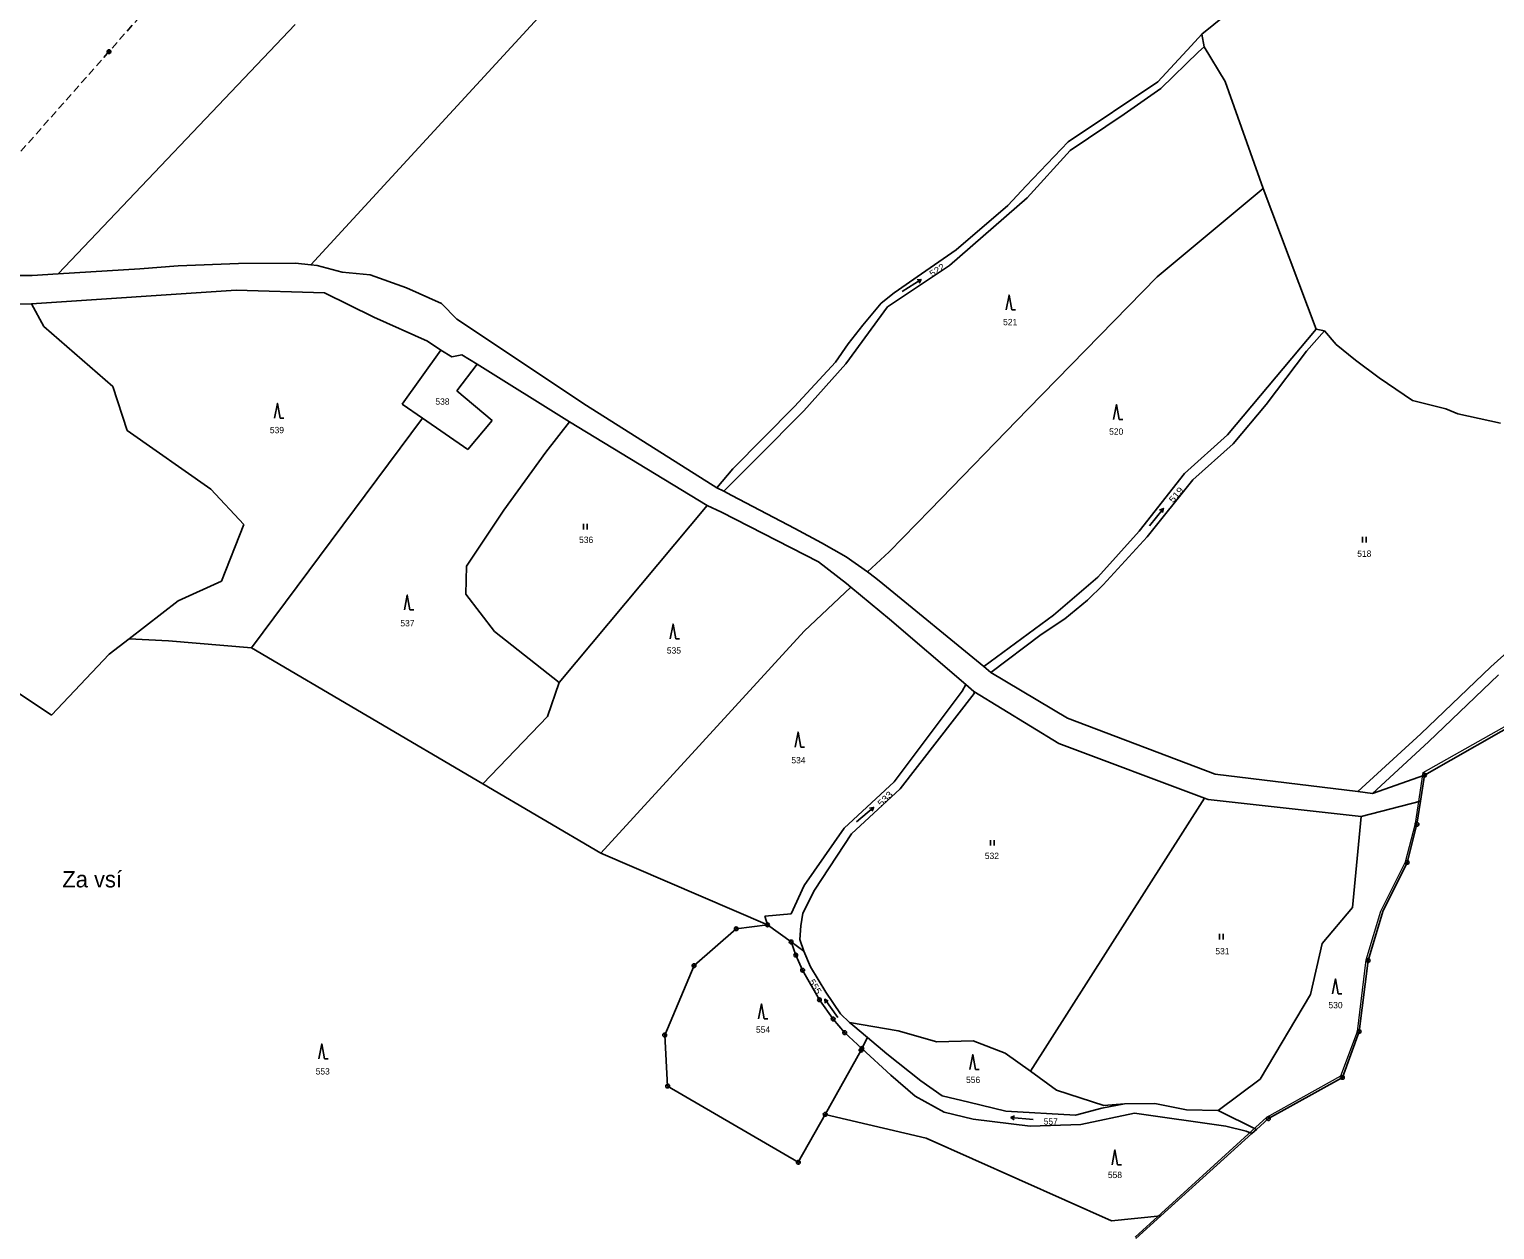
# Model space of a CAD drawing. Extents: x -653193 to -651624, y -1092017 to -1090260.
# Drawn here: x -652409.3 to -652015.8, y -1091464 to -1091141.6 of the extents above; entities that cross this region are included whole.
import ezdxf
from ezdxf.enums import TextEntityAlignment as Align

# ---------------------------------------------------------------- set-up
doc = ezdxf.new("R2010")
doc.units = 0
doc.header["$LTSCALE"] = 0.68
doc.linetypes.add('MEDIUM_DASHED', pattern=[4.5, 3, -1.5])
for name, color, linetype, lineweight in [('1', 7, 'Continuous', 25), ('3', 7, 'Continuous', 25), ('4', 7, 'Continuous', 13), ('6', 7, 'Continuous', 25), ('7', 7, 'Continuous', 13), ('8', 7, 'Continuous', 25)]:
    doc.layers.add(name, color=color, linetype=linetype, lineweight=lineweight)
doc.layers.add('2', color=7, linetype='Continuous')

msp = doc.modelspace()

# ---------------------------------------------------------------- linework, layer by layer
at = {"layer": '1'}
for p, q in [((-652228.92, -1091090.97), (-652333.63, -1091204.87)), ((-652079.85, -1091131.06), (-652094.43, -1091142.88)), ((-652337.88, -1091140.35), (-652401.48, -1091207.32)), ((-652094.43, -1091142.88), (-652097.36, -1091146.07)), ((-652094.43, -1091142.88), (-652093.86, -1091146.31)), ((-652097.36, -1091146.07), (-652106.25, -1091155.76)), ((-652095.39, -1091147.7), (-652105.44, -1091157.47)), ((-652095.39, -1091147.7), (-652093.86, -1091146.31)), ((-652093.86, -1091146.31), (-652088.2, -1091155.67)), ((-652106.25, -1091155.76), (-652130.38, -1091171.83)), ((-652088.2, -1091155.67), (-652077.99, -1091184.36)), ((-652105.44, -1091157.47), (-652115.27, -1091164.38)), ((-652115.27, -1091164.38), (-652129.82, -1091174.14)), ((-652141.61, -1091183.64), (-652130.38, -1091171.83)), ((-652129.82, -1091174.14), (-652141.35, -1091186.91)), ((-652146.54, -1091188.95), (-652141.61, -1091183.64)), ((-652141.35, -1091186.91), (-652162.19, -1091205.06)), ((-652106.45, -1091208.06), (-652077.99, -1091184.36)), ((-652077.99, -1091184.36), (-652063.78, -1091222.16)), ((-652160.45, -1091200.81), (-652146.54, -1091188.95)), ((-652169.72, -1091207.28), (-652160.45, -1091200.81)), ((-652401.48, -1091207.32), (-652408.46, -1091207.73)), ((-652379.6, -1091205.91), (-652401.48, -1091207.32)), ((-652369.33, -1091205.1), (-652379.6, -1091205.91)), ((-652353.05, -1091204.48), (-652369.33, -1091205.1)), ((-652337.79, -1091204.41), (-652353.05, -1091204.48)), ((-652333.63, -1091204.87), (-652337.79, -1091204.41)), ((-652331.97, -1091205.06), (-652333.63, -1091204.87)), ((-652325.27, -1091206.83), (-652331.97, -1091205.06)), ((-652317.78, -1091207.57), (-652325.27, -1091206.83)), ((-652162.19, -1091205.06), (-652178.85, -1091216.18)), ((-652177.03, -1091212.4), (-652169.72, -1091207.28)), ((-652408.46, -1091207.73), (-652457.25, -1091207.83)), ((-652308.03, -1091211.02), (-652317.78, -1091207.57)), ((-652298.61, -1091215.29), (-652308.03, -1091211.02)), ((-652141.13, -1091243.67), (-652106.45, -1091208.06)), ((-652408.71, -1091215.36), (-652486.99, -1091216.11)), ((-652353.69, -1091211.67), (-652408.71, -1091215.36)), ((-652405.35, -1091221.4), (-652408.71, -1091215.36)), ((-652329.96, -1091212.41), (-652353.69, -1091211.67)), ((-652316.74, -1091218.93), (-652329.96, -1091212.41)), ((-652294.44, -1091219.47), (-652298.61, -1091215.29)), ((-652185.51, -1091221.05), (-652180.51, -1091215.2)), ((-652180.51, -1091215.2), (-652177.03, -1091212.4)), ((-652302.39, -1091225.39), (-652316.74, -1091218.93)), ((-652178.85, -1091216.18), (-652190.02, -1091231.46)), ((-652386.83, -1091237.58), (-652405.35, -1091221.4)), ((-652259.65, -1091242.61), (-652294.44, -1091219.47)), ((-652189.45, -1091226.12), (-652185.51, -1091221.05)), ((-652063.78, -1091222.16), (-652087.59, -1091250.54)), ((-652066.34, -1091228.02), (-652061.56, -1091222.57)), ((-652063.78, -1091222.16), (-652061.56, -1091222.57)), ((-652061.56, -1091222.57), (-652058.38, -1091226.27)), ((-652298.78, -1091227.76), (-652302.39, -1091225.39)), ((-652192.79, -1091231.03), (-652189.45, -1091226.12)), ((-652058.38, -1091226.27), (-652053.18, -1091230.52)), ((-652298.78, -1091227.76), (-652309.11, -1091242.27)), ((-652295.85, -1091229.62), (-652298.78, -1091227.76)), ((-652293.09, -1091229.03), (-652295.85, -1091229.62)), ((-652289.05, -1091231.55), (-652293.09, -1091229.03)), ((-652203.79, -1091242.9), (-652192.79, -1091231.03)), ((-652077.15, -1091242.41), (-652066.34, -1091228.02)), ((-652053.18, -1091230.52), (-652046.86, -1091235.25)), ((-652294.48, -1091238.72), (-652289.05, -1091231.55)), ((-652264.25, -1091247.08), (-652289.05, -1091231.55)), ((-652190.02, -1091231.46), (-652201.3, -1091244.07)), ((-652382.98, -1091249.35), (-652386.83, -1091237.58)), ((-652284.97, -1091246.66), (-652294.48, -1091238.72)), ((-652046.86, -1091235.25), (-652037.91, -1091241.32)), ((-652309.11, -1091242.27), (-652303.7, -1091246.05)), ((-652259.65, -1091242.61), (-652224.71, -1091264.77)), ((-652220.4, -1091259.62), (-652203.79, -1091242.9)), ((-652086.07, -1091252.93), (-652077.15, -1091242.41)), ((-652037.91, -1091241.32), (-652028.98, -1091243.53)), ((-652303.7, -1091246.05), (-652349.62, -1091307.76)), ((-652303.7, -1091246.05), (-652291.55, -1091254.5)), ((-652291.55, -1091254.5), (-652284.97, -1091246.66)), ((-652201.3, -1091244.07), (-652213.85, -1091256.68)), ((-652167.42, -1091270.66), (-652141.13, -1091243.67)), ((-652028.98, -1091243.53), (-652025.75, -1091244.89)), ((-652025.75, -1091244.89), (-652014.28, -1091247.38)), ((-652360.49, -1091265.09), (-652382.98, -1091249.35)), ((-652270.6, -1091255.17), (-652264.25, -1091247.08)), ((-652227.23, -1091269.48), (-652264.25, -1091247.08)), ((-652087.59, -1091250.54), (-652099.1, -1091260.92)), ((-652096.85, -1091262.6), (-652086.07, -1091252.93)), ((-652281.84, -1091270.75), (-652270.6, -1091255.17)), ((-652213.85, -1091256.68), (-652222.81, -1091265.7)), ((-652224.71, -1091264.77), (-652220.4, -1091259.62)), ((-652099.1, -1091260.92), (-652111.26, -1091276.41)), ((-652351.65, -1091274.6), (-652360.49, -1091265.09)), ((-652224.71, -1091264.77), (-652222.81, -1091265.7)), ((-652222.81, -1091265.7), (-652220.6, -1091266.79)), ((-652109.12, -1091277.93), (-652096.85, -1091262.6)), ((-652227.23, -1091269.48), (-652267.04, -1091317.02)), ((-652223.42, -1091271.32), (-652227.23, -1091269.48)), ((-652220.6, -1091266.79), (-652203.73, -1091275.7)), ((-652291.88, -1091285.81), (-652281.84, -1091270.75)), ((-652197.39, -1091284.63), (-652223.42, -1091271.32)), ((-652178.38, -1091281.91), (-652167.42, -1091270.66)), ((-652357.7, -1091289.87), (-652351.65, -1091274.6)), ((-652203.73, -1091275.7), (-652196.57, -1091279.52)), ((-652111.26, -1091276.41), (-652122.39, -1091288.72)), ((-652120.99, -1091290.79), (-652109.12, -1091277.93)), ((-652196.57, -1091279.52), (-652189.95, -1091283.32)), ((-652184.24, -1091287.36), (-652178.38, -1091281.91)), ((-652292.07, -1091293.3), (-652291.88, -1091285.81)), ((-652189.86, -1091290.44), (-652197.39, -1091284.63)), ((-652189.95, -1091283.32), (-652184.24, -1091287.36)), ((-652369.26, -1091295.14), (-652357.7, -1091289.87)), ((-652184.24, -1091287.36), (-652181.98, -1091289.04)), ((-652181.98, -1091289.04), (-652180.1, -1091290.56)), ((-652122.39, -1091288.72), (-652134.26, -1091299)), ((-652284.37, -1091303.32), (-652292.07, -1091293.3)), ((-652201.23, -1091303.24), (-652188.66, -1091291.44)), ((-652188.66, -1091291.44), (-652189.86, -1091290.44)), ((-652178.33, -1091300.04), (-652188.66, -1091291.44)), ((-652180.1, -1091290.56), (-652152.95, -1091312.77)), ((-652125.18, -1091294.96), (-652120.99, -1091290.79)), ((-652382.43, -1091305.33), (-652369.26, -1091295.14)), ((-652131.28, -1091299.91), (-652125.18, -1091294.96)), ((-652157.79, -1091317.57), (-652178.33, -1091300.04)), ((-652134.26, -1091299), (-652152.95, -1091312.77)), ((-652137.62, -1091304.11), (-652131.28, -1091299.91)), ((-652382.43, -1091305.33), (-652387.79, -1091309.41)), ((-652371.87, -1091305.83), (-652382.43, -1091305.33)), ((-652349.62, -1091307.76), (-652371.87, -1091305.83)), ((-652267.04, -1091317.02), (-652284.37, -1091303.32)), ((-652255.81, -1091362.84), (-652201.23, -1091303.24)), ((-652151.1, -1091314.32), (-652137.62, -1091304.11)), ((-652016.85, -1091312.8), (-652007.17, -1091304.16)), ((-652387.79, -1091309.41), (-652403.34, -1091325.86)), ((-652287.5, -1091344.23), (-652349.62, -1091307.76)), ((-652152.95, -1091312.77), (-652151.1, -1091314.32)), ((-652035.62, -1091330.83), (-652016.85, -1091312.8)), ((-652403.34, -1091325.86), (-652416.58, -1091316.92)), ((-652270.13, -1091326.19), (-652267.04, -1091317.02)), ((-652158.81, -1091319.38), (-652157.79, -1091317.57)), ((-652155.63, -1091319.42), (-652157.79, -1091317.57)), ((-652130.5, -1091326.62), (-652151.1, -1091314.32)), ((-652034.65, -1091341.96), (-651991.83, -1091317.47)), ((-652014.81, -1091315), (-652033.57, -1091333.02)), ((-652177.07, -1091343.7), (-652158.81, -1091319.38)), ((-652155.56, -1091320.01), (-652175.47, -1091345.58)), ((-652155.63, -1091319.42), (-652155.56, -1091320.01)), ((-652132.81, -1091333.44), (-652155.63, -1091319.42)), ((-652287.5, -1091344.23), (-652270.13, -1091326.19)), ((-652090.86, -1091341.62), (-652130.5, -1091326.62)), ((-652052.57, -1091346.36), (-652035.62, -1091330.83)), ((-652033.57, -1091333.02), (-652048.68, -1091346.84)), ((-652093.75, -1091348.11), (-652132.81, -1091333.44)), ((-652255.81, -1091362.84), (-652287.5, -1091344.23)), ((-652190.51, -1091356.19), (-652177.07, -1091343.7)), ((-652052.57, -1091346.36), (-652090.86, -1091341.62)), ((-652048.68, -1091346.84), (-652034.65, -1091341.96)), ((-652035.73, -1091348.93), (-652034.65, -1091341.96)), ((-652175.47, -1091345.58), (-652188.49, -1091357.67)), ((-652140.49, -1091421.45), (-652093.75, -1091348.11)), ((-652092.78, -1091348.48), (-652093.75, -1091348.11)), ((-652051.71, -1091353.06), (-652092.78, -1091348.48)), ((-652048.68, -1091346.84), (-652052.57, -1091346.36)), ((-652035.73, -1091348.93), (-652051.71, -1091353.06)), ((-652036.7, -1091355.13), (-652035.73, -1091348.93)), ((-652051.71, -1091353.06), (-652054.03, -1091377.47)), ((-652201.19, -1091371.59), (-652190.51, -1091356.19)), ((-652039.3, -1091365.37), (-652036.7, -1091355.13)), ((-652188.49, -1091357.67), (-652198.41, -1091372.79)), ((-652211.05, -1091382.12), (-652255.81, -1091362.84)), ((-652045.88, -1091378.54), (-652039.3, -1091365.37)), ((-652204.74, -1091379.18), (-652201.19, -1091371.59)), ((-652198.41, -1091372.79), (-652201.58, -1091378.98)), ((-652211.74, -1091379.78), (-652204.74, -1091379.18)), ((-652211.05, -1091382.12), (-652211.74, -1091379.78)), ((-652201.58, -1091378.98), (-652202.16, -1091382.36)), ((-652054.03, -1091377.47), (-652062.17, -1091387.1)), ((-652049.78, -1091391.7), (-652045.88, -1091378.54)), ((-652230.79, -1091393.09), (-652219.45, -1091383.17)), ((-652219.45, -1091383.17), (-652211.05, -1091382.12)), ((-652204.72, -1091386.73), (-652211.05, -1091382.12)), ((-652202.16, -1091382.36), (-652202.41, -1091386.09)), ((-652203.48, -1091390.25), (-652204.72, -1091386.73)), ((-652204.72, -1091386.73), (-652201.28, -1091389.23)), ((-652202.41, -1091386.09), (-652201.28, -1091389.23)), ((-652062.17, -1091387.1), (-652065.27, -1091400.81)), ((-652201.63, -1091394.33), (-652203.48, -1091390.25)), ((-652201.28, -1091389.23), (-652199.55, -1091393.38)), ((-652052.22, -1091410.79), (-652049.78, -1091391.7)), ((-652238.67, -1091411.72), (-652230.79, -1091393.09)), ((-652197.13, -1091402.26), (-652201.63, -1091394.33)), ((-652199.55, -1091393.38), (-652195.4, -1091400.21)), ((-652195.4, -1091400.21), (-652191.49, -1091405.99)), ((-652193.44, -1091407.42), (-652197.13, -1091402.26)), ((-652065.27, -1091400.81), (-652078.79, -1091423.58)), ((-652190.35, -1091411.08), (-652193.44, -1091407.42)), ((-652191.49, -1091405.99), (-652189.08, -1091408.4)), ((-652237.88, -1091425.42), (-652238.67, -1091411.72)), ((-652185.71, -1091415.32), (-652190.35, -1091411.08)), ((-652175.99, -1091410.63), (-652189.08, -1091408.4)), ((-652189.08, -1091408.4), (-652188.18, -1091409.11)), ((-652188.18, -1091409.11), (-652184.25, -1091412.43)), ((-652165.56, -1091413.51), (-652175.99, -1091410.63)), ((-652056.71, -1091423.1), (-652052.22, -1091410.79)), ((-652195.59, -1091433.03), (-652185.95, -1091415.8)), ((-652185.95, -1091415.8), (-652185.71, -1091415.32)), ((-652185.71, -1091415.32), (-652184.25, -1091412.43)), ((-652177.91, -1091422.47), (-652185.71, -1091415.32)), ((-652184.25, -1091412.43), (-652179.07, -1091416.8)), ((-652155.88, -1091413.31), (-652165.56, -1091413.51)), ((-652147.27, -1091416.57), (-652155.88, -1091413.31)), ((-652179.07, -1091416.8), (-652169.9, -1091423.98)), ((-652140.49, -1091421.45), (-652147.27, -1091416.57)), ((-652171.41, -1091428.14), (-652177.91, -1091422.47)), ((-652133.45, -1091426.52), (-652140.49, -1091421.45)), ((-652078.79, -1091423.58), (-652090.08, -1091432.01)), ((-652076.58, -1091434.18), (-652056.71, -1091423.1)), ((-652202.79, -1091445.9), (-652237.88, -1091425.42)), ((-652169.9, -1091423.98), (-652164.16, -1091428.05)), ((-652120.77, -1091430.69), (-652133.45, -1091426.52)), ((-652163.62, -1091432.46), (-652171.41, -1091428.14)), ((-652164.16, -1091428.05), (-652157.03, -1091429.78)), ((-652157.03, -1091429.78), (-652147.09, -1091432.21)), ((-652128.37, -1091433.26), (-652121.34, -1091431.37)), ((-652121.34, -1091431.37), (-652115.24, -1091430.16)), ((-652115.24, -1091430.16), (-652120.77, -1091430.69)), ((-652115.24, -1091430.16), (-652107.1, -1091430.09)), ((-652107.1, -1091430.09), (-652098.54, -1091431.8)), ((-652195.59, -1091433.03), (-652202.79, -1091445.9)), ((-652168.46, -1091439.44), (-652195.59, -1091433.03)), ((-652155.84, -1091434.32), (-652163.62, -1091432.46)), ((-652140.59, -1091436.23), (-652155.84, -1091434.32)), ((-652147.09, -1091432.21), (-652128.37, -1091433.26)), ((-652112.51, -1091432.69), (-652126.93, -1091435.77)), ((-652087.97, -1091436.16), (-652112.51, -1091432.69)), ((-652098.54, -1091431.8), (-652090.08, -1091432.01)), ((-652090.08, -1091432.01), (-652079.76, -1091437.05)), ((-652079.76, -1091437.05), (-652076.58, -1091434.18)), ((-652118.68, -1091461.65), (-652168.46, -1091439.44)), ((-652126.93, -1091435.77), (-652140.59, -1091436.23)), ((-652105.44, -1091460.25), (-652081.02, -1091438.19)), ((-652082.59, -1091437.55), (-652087.97, -1091436.16)), ((-652081.02, -1091438.19), (-652082.59, -1091437.55)), ((-652081.02, -1091438.19), (-652079.76, -1091437.05)), ((-652105.44, -1091460.25), (-652118.68, -1091461.65)), ((-652112.2, -1091466.36), (-652105.44, -1091460.25))]:
    msp.add_line(p, q, dxfattribs=at)
at = {"layer": '3'}
for p, q in [((-652169.817, -1091208.818), (-652170.38, -1091209.761)), ((-652145.46, -1091216.98), (-652144.464, -1091216.98)), ((-652341.91, -1091246.07), (-652340.914, -1091246.07)), ((-652116.63, -1091246.4), (-652115.634, -1091246.4)), ((-652104.775, -1091270.301), (-652105, -1091271.376)), ((-652260.461, -1091275.95), (-652260.461, -1091274.45)), ((-652259.46, -1091275.95), (-652259.46, -1091274.45)), ((-652051.341, -1091279.43), (-652051.341, -1091277.93)), ((-652050.34, -1091279.43), (-652050.34, -1091277.93)), ((-652307.05, -1091297.57), (-652306.054, -1091297.57)), ((-652235.68, -1091305.35), (-652234.684, -1091305.35)), ((-652202.12, -1091334.37), (-652201.124, -1091334.37)), ((-652182.583, -1091350.587), (-652183.009, -1091351.599)), ((-652151.211, -1091360.86), (-652151.211, -1091359.36)), ((-652150.21, -1091360.86), (-652150.21, -1091359.36)), ((-652089.701, -1091386.08), (-652089.701, -1091384.58)), ((-652088.7, -1091386.08), (-652088.7, -1091384.58)), ((-652195.716, -1091402.124), (-652194.736, -1091402.62)), ((-652057.86, -1091400.64), (-652056.864, -1091400.64)), ((-652211.95, -1091407.37), (-652210.954, -1091407.37)), ((-652330.01, -1091418.1), (-652329.014, -1091418.1)), ((-652155.21, -1091420.98), (-652154.214, -1091420.98)), ((-652145.735, -1091433.879), (-652144.718, -1091433.464)), ((-652117.06, -1091446.57), (-652116.064, -1091446.57))]:
    msp.add_line(p, q, dxfattribs=at)
for points in [[(-652174.905, -1091211.998), (-652169.817, -1091208.818), (-652170.911, -1091208.911)], [(-652145.46, -1091216.98), (-652146.21, -1091212.98), (-652146.96, -1091216.98)], [(-652341.91, -1091246.07), (-652342.66, -1091242.07), (-652343.41, -1091246.07)], [(-652116.63, -1091246.4), (-652117.38, -1091242.4), (-652118.13, -1091246.4)], [(-652108.551, -1091274.964), (-652104.775, -1091270.301), (-652105.779, -1091270.744)], [(-652307.05, -1091297.57), (-652307.8, -1091293.57), (-652308.55, -1091297.57)], [(-652235.68, -1091305.35), (-652236.43, -1091301.35), (-652237.18, -1091305.35)], [(-652202.12, -1091334.37), (-652202.87, -1091330.37), (-652203.62, -1091334.37)], [(-652187.179, -1091354.444), (-652182.583, -1091350.587), (-652183.654, -1091350.831)], [(-652057.86, -1091400.64), (-652058.61, -1091396.64), (-652059.36, -1091400.64)], [(-652211.95, -1091407.37), (-652212.7, -1091403.37), (-652213.45, -1091407.37)], [(-652192.19, -1091406.978), (-652195.716, -1091402.124), (-652195.548, -1091403.209)], [(-652330.01, -1091418.1), (-652330.76, -1091414.1), (-652331.51, -1091418.1)], [(-652155.21, -1091420.98), (-652155.96, -1091416.98), (-652156.71, -1091420.98)], [(-652139.758, -1091434.401), (-652145.735, -1091433.879), (-652144.805, -1091434.463)], [(-652117.06, -1091446.57), (-652117.81, -1091442.57), (-652118.56, -1091446.57)]]:
    msp.add_lwpolyline(points, dxfattribs=at)
at = {"layer": '4'}
msp.add_lwpolyline([(-652112.38, -1091466.02), (-652077.01, -1091433.77), (-652057.15, -1091422.69), (-652052.66, -1091410.79), (-652050.37, -1091391.5), (-652046.36, -1091378.45), (-652039.77, -1091365.22), (-652037.1, -1091354.95), (-652035, -1091341.19), (-651992.17, -1091317.02)], dxfattribs=at)
at = {"layer": '6', "linetype": 'MEDIUM_DASHED'}
for p, q in [((-652339.17, -1091092.32), (-652387.86, -1091147.62)), ((-652387.86, -1091147.62), (-652435.98, -1091202.04))]:
    msp.add_line(p, q, dxfattribs=at)
at = {"layer": '6'}
for radius in [0.5, 0.4, 0.3, 0.2, 0.1]:
    msp.add_circle((-652387.8634, -1091147.6199), radius, dxfattribs=at)
at = {"layer": '8'}
for centre, radius in [((-652034.65, -1091341.9599), 0.5), ((-652034.65, -1091341.9599), 0.0303), ((-652036.7, -1091355.1299), 0.5), ((-652036.7, -1091355.1299), 0.0303), ((-652039.3, -1091365.3699), 0.5), ((-652039.3, -1091365.3699), 0.0303), ((-652219.45, -1091383.1699), 0.5), ((-652219.45, -1091383.1699), 0.0303), ((-652211.05, -1091382.1199), 0.5), ((-652211.05, -1091382.1199), 0.0303), ((-652204.72, -1091386.7299), 0.5), ((-652204.72, -1091386.7299), 0.0303), ((-652203.48, -1091390.2499), 0.5), ((-652203.48, -1091390.2499), 0.0303), ((-652049.78, -1091391.6999), 0.5), ((-652049.78, -1091391.6999), 0.0303), ((-652230.79, -1091393.0899), 0.5), ((-652230.79, -1091393.0899), 0.0303), ((-652201.63, -1091394.3299), 0.5), ((-652201.63, -1091394.3299), 0.0303), ((-652197.13, -1091402.2599), 0.5), ((-652197.13, -1091402.2599), 0.0303), ((-652193.44, -1091407.4199), 0.5), ((-652193.44, -1091407.4199), 0.0303), ((-652238.67, -1091411.7199), 0.5), ((-652238.67, -1091411.7199), 0.0303), ((-652190.35, -1091411.0799), 0.5), ((-652190.35, -1091411.0799), 0.0303), ((-652052.22, -1091410.7899), 0.5), ((-652052.22, -1091410.7899), 0.0303), ((-652185.95, -1091415.7999), 0.5), ((-652185.71, -1091415.3199), 0.5), ((-652185.95, -1091415.7999), 0.0303), ((-652185.71, -1091415.3199), 0.0303), ((-652056.71, -1091423.0999), 0.5), ((-652056.71, -1091423.0999), 0.0303), ((-652237.88, -1091425.4199), 0.5), ((-652237.88, -1091425.4199), 0.0303), ((-652195.59, -1091433.0299), 0.5), ((-652195.59, -1091433.0299), 0.0303), ((-652076.58, -1091434.1799), 0.5), ((-652076.58, -1091434.1799), 0.0303), ((-652202.79, -1091445.8999), 0.5), ((-652202.79, -1091445.8999), 0.0303)]:
    msp.add_circle(centre, radius, dxfattribs=at)

# ---------------------------------------------------------------- texts
at = {"layer": '2'}
for s, rotation, width, p in [('522', 33, 1.15, (-652165.0724, -1091207.0131)), ('519', 50, 1.2, (-652100.7002, -1091267.1844)), ('533', 45, 1.2, (-652178.9025, -1091348.8635)), ('555', 301, 1.1, (-652198.9502, -1091399.1417))]:
    msp.add_text(s, height=1.7, rotation=rotation, dxfattribs=dict(at, width=width)).set_placement(p, align=Align.CENTER)
for s, p in [('521', (-652145.909, -1091221.095)), ('538', (-652298.329, -1091242.435)), ('539', (-652342.769, -1091250.095)), ('520', (-652117.439, -1091250.505)), ('536', (-652259.749, -1091279.575)), ('518', (-652050.839, -1091283.295)), ('537', (-652307.739, -1091301.975)), ('535', (-652236.189, -1091309.275)), ('534', (-652202.759, -1091338.765)), ('532', (-652150.819, -1091364.455)), ('531', (-652088.929, -1091390.065)), ('530', (-652058.559, -1091404.535)), ('554', (-652212.269, -1091411.115)), ('553', (-652330.479, -1091422.325)), ('556', (-652155.859, -1091424.605)), ('557', (-652135.019, -1091435.785)), ('558', (-652117.779, -1091450.145))]:
    msp.add_text(s, height=1.7, dxfattribs=at).set_placement(p, align=Align.CENTER)
at = {"layer": '7'}
msp.add_text('Za vsí', height=4.4, dxfattribs=at).set_placement((-652392.379, -1091372.08), align=Align.CENTER)

doc.saveas('drawing.dxf')
